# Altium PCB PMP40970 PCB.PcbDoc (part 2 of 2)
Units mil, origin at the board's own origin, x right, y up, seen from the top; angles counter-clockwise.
Board outline 1445 x 1417.32 mil, 2 copper layers (Top Layer, Bottom Layer), stack 64.8 mil thick; 72 components, 33 nets, 177 pads, 86 vias.
Unrouted connection lines stored in the file: 44.
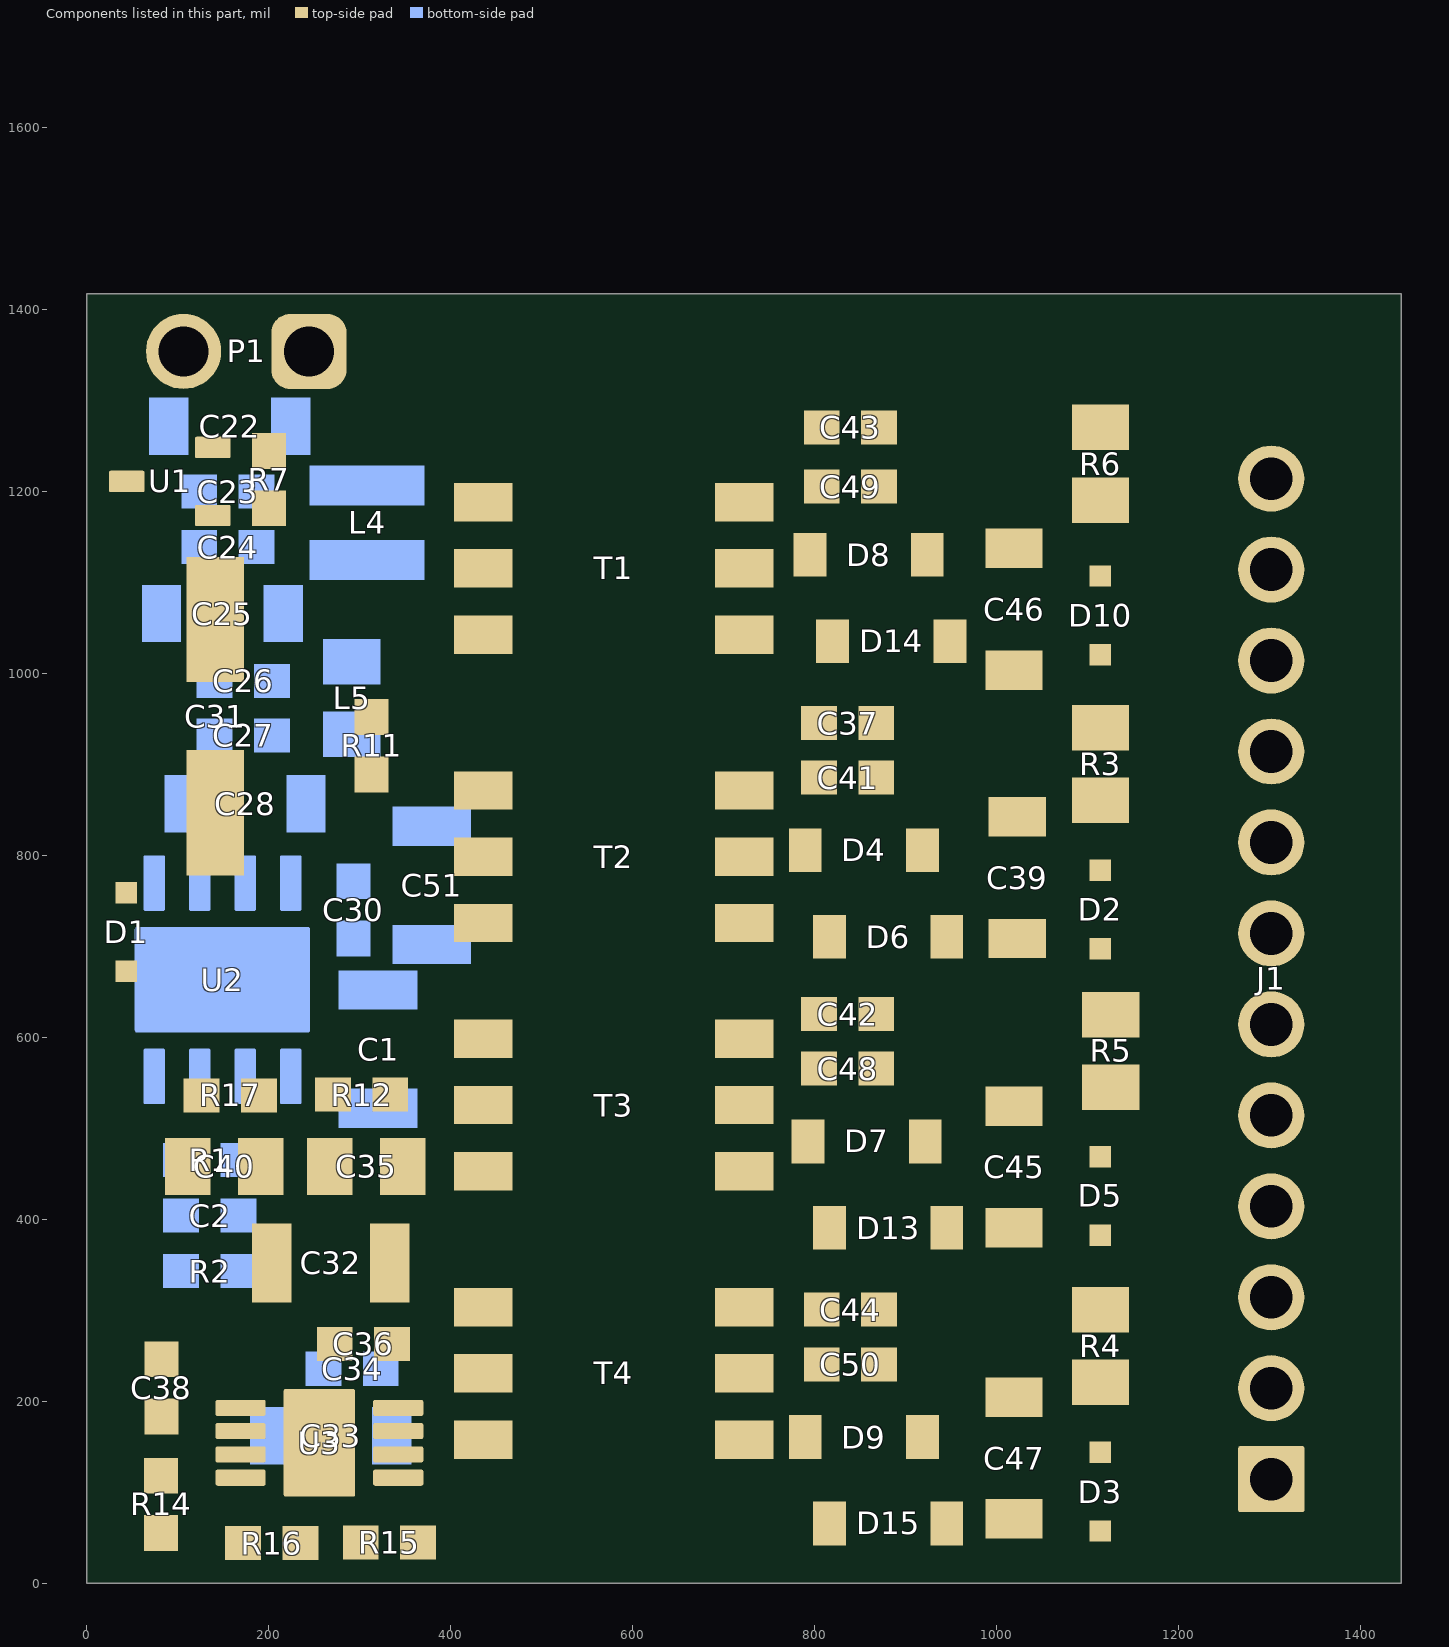
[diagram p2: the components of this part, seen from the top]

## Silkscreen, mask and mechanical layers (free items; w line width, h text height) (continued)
M12 Stackup:
  drawing of 191 lines, arcs and shapes, not listed
  text "Layer" at 9750.58,7810 h60
  text "Name" at 10160.49,7810 h60
  text "Material" at 11090.23,7810 h60
  text "Thickness" at 11950,7810 h60
  text "Constant" at 12599.84,7810 h60
  text "Board Layer Stack" at 13169.7,7810 h60
  text "1" at 9750.58,7690 h60
  text "Top Overlay" at 10160.49,7690 h60
  text "2" at 9750.58,7570 h60
  text "Top Solder" at 10160.49,7570 h60
  text "Solder Resist" at 11090.23,7570 h60
  text "0.40mil" at 11950,7570 h60
  text "3.5" at 12599.84,7570 h60
  text "3" at 9750.58,7450 h60
  text "Top Layer" at 10160.49,7450 h60
  text "Copper" at 11090.23,7450 h60
  text "2.80mil" at 11950,7450 h60
  text "4" at 9750.58,7330 h60
  text "Dielectric1" at 10160.49,7330 h60
  text "FR-4 High Tg" at 11090.23,7330 h60
  text "59.20mil" at 11950,7330 h60
  text "4.8" at 12599.84,7330 h60
  text "5" at 9750.58,7210 h60
  text "Bottom Layer" at 10160.49,7210 h60
  text "Copper" at 11090.23,7210 h60
  text "2.80mil" at 11950,7210 h60
  text "6" at 9750.58,7090 h60
  text "Bottom Solder" at 10160.49,7090 h60
  text "Solder Resist" at 11090.23,7090 h60
  text "0.40mil" at 11950,7090 h60
  text "3.5" at 12599.84,7090 h60
  text "7" at 9750.58,6970 h60
  text "Bottom Overlay" at 10160.49,6970 h60
  text ".Layer_Name" at 577,-858.49 h60
M13 Component Bodies Top:
  text ".Layer_Name" at 577,-858.49 h60
M14 Component Bodies Bottom:
  text ".Layer_Name" at 577,-858.49 h60
M15 Courtyards Top:
  text ".Layer_Name" at 577,-858.49 h60
M16 Courtyards Bottom:
  text ".Layer_Name" at 577,-858.49 h60
Drill Drawing:
  lines w10: 4126.09,2487.7 4153.72,2501.51 4181.34,2487.7 4167.53,2515.32 4181.34,2542.95 4153.72,2529.14 4126.09,2542.95 4139.9,2515.32 4126.09,2487.7 ; 4126.09,2612.02 4181.34,2612.02 4181.34,2667.27 4126.09,2667.27 4126.09,2612.02 ; 4126.09,2750.15 4139.9,2750.15 4139.9,2736.34 4167.53,2736.34 4167.53,2750.15 4181.34,2750.15 4181.34,2777.78 4167.53,2777.78 4167.53,2791.59 4139.9,2791.59 4139.9,2777.78 4126.09,2777.78 4126.09,2750.15 ; 4126.09,2874.47 4139.9,2874.47 4153.72,2860.66 4167.53,2874.47 4181.34,2874.47 4167.53,2888.28 4181.34,2902.1 4167.53,2902.1 4153.72,2915.91 4139.9,2902.1 4126.09,2902.1 4139.9,2888.28 4126.09,2874.47
  lines w12: 4076,2450.4 7307.49,2450.4 ; 4076,2947.68 7307.49,2947.68 ; 4413.86,2326.08 4413.86,3072 ; 4745.86,2326.08 4745.86,3072 ; 5382.43,2326.08 5382.43,3072 ; 5641.57,2326.08 5641.57,3072 ; 6016.72,2326.08 6016.72,3072 ; 6741.05,2326.08 6741.05,3072 ; 4076,2326.08 7307.49,2326.08 7307.49,3072 4076,3072 4076,2326.08
  text "Symbol" at 4150.59,2984.98 h72
  text "Quantity" at 4451.16,2984.98 h72
  text "Finished Hole Size" at 4783.16,2984.98 h72
  text "Plated" at 5419.72,2984.98 h72
  text "Hole Type" at 5678.86,2984.98 h72
  text "Drill Layer Pair" at 6054.02,2984.98 h72
  text "Hole Tolerance" at 6778.35,2984.98 h72
  text "14" at 4451.16,2860.66 h60
  text "7.87mil (0.200mm)" at 4783.16,2860.66 h60
  text "PTH" at 5419.72,2860.66 h60
  text "Round" at 5678.86,2860.66 h60
  text "Top Layer - Bottom Layer" at 6054.02,2860.66 h60
  text "72" at 4451.16,2736.34 h60
  text "10.00mil (0.254mm)" at 4783.16,2736.34 h60
  text "PTH" at 5419.72,2736.34 h60
  text "Round" at 5678.86,2736.34 h60
  text "Top Layer - Bottom Layer" at 6054.02,2736.34 h60
  text "12" at 4451.16,2612.02 h60
  text "47.00mil (1.194mm)" at 4783.16,2612.02 h60
  text "PTH" at 5419.72,2612.02 h60
  text "Round" at 5678.86,2612.02 h60
  text "Top Layer - Bottom Layer" at 6054.02,2612.02 h60
  text "2" at 4451.16,2487.7 h60
  text "55.12mil (1.400mm)" at 4783.16,2487.7 h60
  text "PTH" at 5419.72,2487.7 h60
  text "Round" at 5678.86,2487.7 h60
  text "Top Layer - Bottom Layer" at 6054.02,2487.7 h60
  text "100 Total" at 4451.16,2363.38 h60
  text ".Layer_Name" at 577,-858.49 h60
M17 Embedded Cavity:
  text ".Layer_Name" at 577,-858.49 h60
M18 Embedded Assembly:
  text ".Layer_Name" at 577,-858.49 h60
M19 Embedded Keepout:
  text ".Layer_Name" at 577,-858.49 h60

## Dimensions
0,0 to 1445,0 on M2 Board Dimensions
0,0 to 0,1417.32 on M2 Board Dimensions
0,-400 to 1000,-400 on M2 Board Dimensions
